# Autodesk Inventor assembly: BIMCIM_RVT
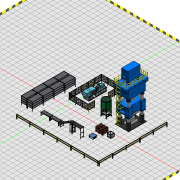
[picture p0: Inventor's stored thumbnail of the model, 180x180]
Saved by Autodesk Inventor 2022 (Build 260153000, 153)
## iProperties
Created: 2021-04
Part Number: BIMCIM_RVT
Document SubType Name: Assembly
Designer: shimont
Author: shimont
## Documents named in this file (16)
- C:\Users\shimont\Desktop\Inventor2022_BIMCIM出力\Inventor_Data\Workspaces\作業スペース\BIMCIM_RVT.iam
- C:\Users\shimont\Desktop\Inventor2022_BIMCIM出力\Inventor_Data\Workspaces\作業スペース\Factory Assets\Straight Belt Conveyor_62AB7746C87F18CB2B8D9DA90091859B.ipt
- C:\Users\shimont\Desktop\Inventor2022_BIMCIM出力\Inventor_Data\Workspaces\作業スペース\Factory Assets\Inclined Belt Conveyor_BBAA08BEB62DBBBFF53098BD601E2EAB.ipt
- C:\Users\shimont\Desktop\Inventor2022_BIMCIM出力\Inventor_Data\Workspaces\作業スペース\Factory Assets\Straight Belt Conveyor_1305EE5B90894E3F8A0AC29B882C3BD2.ipt
- C:\Users\shimont\Desktop\Inventor2022_BIMCIM出力\Inventor_Data\Workspaces\作業スペース\Factory Assets\Guard Rail_DAA5105E75A682DEC81597EA9AEDF0DA.ipt
- C:\Users\shimont\Desktop\Inventor2022_BIMCIM出力\Inventor_Data\Workspaces\作業スペース\Factory Assets\Guard Rail (Turn)_2788CAD562E2371D18F7DFFD656164ED.ipt
- C:\Users\shimont\Desktop\Inventor2022_BIMCIM出力\Inventor_Data\Workspaces\作業スペース\Factory Assets\Crate_83A1AEDB755784B46B9D26325E66DF3A.ipt
- C:\Users\shimont\Desktop\Inventor2022_BIMCIM出力\Inventor_Data\Workspaces\作業スペース\Factory Assets\Container (Mesh)_BC0053C154BD38D42D015A9FC74D4A9F.ipt
- C:\Users\shimont\Desktop\Inventor2022_BIMCIM出力\Inventor_Data\Workspaces\作業スペース\Factory Assets\Rack_49CEDE8AAA8C23DD442531F5BABC324C.ipt
- C:\Users\shimont\Desktop\Inventor2022_BIMCIM出力\Inventor_Data\Workspaces\作業スペース\Factory Assets\Lift Table_ED15CC229C601761F49F94E97E517109.ipt
- C:\Users\shimont\Desktop\Inventor2022_BIMCIM出力\Inventor_Data\Workspaces\作業スペース\Factory Assets\Forging Hydraulic Press_FF96057043D5FA31CE447ECF96B5AD74.ipt
- C:\Users\shimont\Desktop\Inventor2022_BIMCIM出力\Inventor_Data\Workspaces\作業スペース\Factory Assets\Vertical Blender_B7AA12CF308581BABF2536DA422488B5.ipt
- C:\Users\shimont\Desktop\Inventor2022_BIMCIM出力\Inventor_Data\Workspaces\作業スペース\Factory Assets\Injection Molding Machine_A8809DB1706EB9883261279B6DADA9EB.ipt
- C:\Users\shimont\Desktop\Inventor2022_BIMCIM出力\Inventor_Data\Workspaces\作業スペース\Factory Assets\Safety Fence (Turn For Asset Chains)_3DAE86F1382E41C33ACF8F022E66FD50.ipt
- C:\Users\shimont\Desktop\Inventor2022_BIMCIM出力\Inventor_Data\Workspaces\作業スペース\Factory Assets\Safety Fence (For Asset Chains)_EBBD1099C046A123A3332DC6DA49EF25.ipt
- C:\Users\shimont\Desktop\Inventor2022_BIMCIM出力\Inventor_Data\Workspaces\作業スペース\Factory Assets\Safety Fence (Turn)_AE1384E2C6E4AEBE8A5180D575C7EB08.ipt
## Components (21 placed, 14 different names)
1. 直進ベルト コンベア:1 — 直進ベルト コンベア:1_Floor, フラッシュ:2, メイト:1, メイト:2
2. 直進ベルト コンベア:2 — フラッシュ:2, メイト:1, メイト:2, フラッシュ:3, メイト:3, メイト:4
3. 傾斜ベルト コンベア:1 — フラッシュ:3, メイト:3, メイト:4, フラッシュ:4, メイト:5, メイト:6
4. 直進ベルト コンベア:3 — フラッシュ:4, メイト:5, メイト:6
5. ガード レール:1 — ガード レール:1_Floor, フラッシュ:5, メイト:8, メイト:9
6. ガード レール:2 — フラッシュ:5, メイト:8, メイト:9, フラッシュ:6, メイト:10, メイト:11
7. ガード レール(ターン):1 — フラッシュ:6, メイト:10, メイト:11, フラッシュ:7, メイト:12, メイト:13
8. ガード レール:3 — フラッシュ:7, メイト:12, メイト:13, フラッシュ:9, メイト:22, メイト:23
9. クレート:1 — クレート:1_Floor
10. コンテナ(メッシュ):1 — コンテナ(メッシュ):1_Floor
11. ラック:1 — ラック:1_Floor
12. リフト テーブル:1
13. 油圧式鍛造プレス:1
14. 垂直ブレンダ:1
15. インジェクション モールディング マシン:1
16. ガード レール:4 — フラッシュ:9, メイト:22, メイト:23
17. 安全柵(アセット チェーン用のターン):1 — 安全柵(アセット チェーン用のターン):1_Floor, フラッシュ:10, メイト:25, メイト:26, フラッシュ:13, メイト:31, メイト:32
18. 安全柵(アセット チェーン用):1 — フラッシュ:10, メイト:25, メイト:26, フラッシュ:11, メイト:27, メイト:28
19. 安全柵(アセット チェーン用のターン):2 — フラッシュ:11, メイト:27, メイト:28, フラッシュ:12, メイト:29, メイト:30
20. 安全柵(アセット チェーン用のターン):3 — フラッシュ:12, メイト:29, メイト:30
21. 安全柵(ターン):1 — フラッシュ:13, メイト:31, メイト:32
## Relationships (39: Mate 27, Flush 12)
- 直進ベルト コンベア:1_Floor [Flush]: 直進ベルト コンベア:1
- フラッシュ:2 [Flush]: 直進ベルト コンベア:1 ↔ 直進ベルト コンベア:2
- メイト:1 [Mate]: 直進ベルト コンベア:1 ↔ 直進ベルト コンベア:2
- メイト:2 [Mate]: 直進ベルト コンベア:1 ↔ 直進ベルト コンベア:2
- フラッシュ:3 [Flush]: 直進ベルト コンベア:2 ↔ 傾斜ベルト コンベア:1
- メイト:3 [Mate]: 直進ベルト コンベア:2 ↔ 傾斜ベルト コンベア:1
- メイト:4 [Mate]: 直進ベルト コンベア:2 ↔ 傾斜ベルト コンベア:1
- フラッシュ:4 [Flush]: 傾斜ベルト コンベア:1 ↔ 直進ベルト コンベア:3
- メイト:5 [Mate]: 傾斜ベルト コンベア:1 ↔ 直進ベルト コンベア:3
- メイト:6 [Mate]: 傾斜ベルト コンベア:1 ↔ 直進ベルト コンベア:3
- ガード レール:1_Floor [Mate]: ガード レール:1
- フラッシュ:5 [Flush]: ガード レール:1 ↔ ガード レール:2
- メイト:8 [Mate]: ガード レール:1 ↔ ガード レール:2
- メイト:9 [Mate]: ガード レール:1 ↔ ガード レール:2
- フラッシュ:6 [Flush]: ガード レール:2 ↔ ガード レール(ターン):1
- メイト:10 [Mate]: ガード レール:2 ↔ ガード レール(ターン):1
- メイト:11 [Mate]: ガード レール:2 ↔ ガード レール(ターン):1
- フラッシュ:7 [Flush]: ガード レール(ターン):1 ↔ ガード レール:3
- メイト:12 [Mate]: ガード レール(ターン):1 ↔ ガード レール:3
- メイト:13 [Mate]: ガード レール(ターン):1 ↔ ガード レール:3
- クレート:1_Floor [Mate]: クレート:1
- コンテナ(メッシュ):1_Floor [Mate]: コンテナ(メッシュ):1
- ラック:1_Floor [Mate]: ラック:1
- フラッシュ:9 [Flush]: ガード レール:3 ↔ ガード レール:4
- メイト:22 [Mate]: ガード レール:3 ↔ ガード レール:4
- メイト:23 [Mate]: ガード レール:3 ↔ ガード レール:4
- 安全柵(アセット チェーン用のターン):1_Floor [Mate]: 安全柵(アセット チェーン用のターン):1
- フラッシュ:10 [Flush]: 安全柵(アセット チェーン用のターン):1 ↔ 安全柵(アセット チェーン用):1
- メイト:25 [Mate]: 安全柵(アセット チェーン用のターン):1 ↔ 安全柵(アセット チェーン用):1
- メイト:26 [Mate]: 安全柵(アセット チェーン用のターン):1 ↔ 安全柵(アセット チェーン用):1
- フラッシュ:11 [Flush]: 安全柵(アセット チェーン用):1 ↔ 安全柵(アセット チェーン用のターン):2
- メイト:27 [Mate]: 安全柵(アセット チェーン用):1 ↔ 安全柵(アセット チェーン用のターン):2
- メイト:28 [Mate]: 安全柵(アセット チェーン用):1 ↔ 安全柵(アセット チェーン用のターン):2
- フラッシュ:12 [Flush]: 安全柵(アセット チェーン用のターン):2 ↔ 安全柵(アセット チェーン用のターン):3
- メイト:29 [Mate]: 安全柵(アセット チェーン用のターン):2 ↔ 安全柵(アセット チェーン用のターン):3
- メイト:30 [Mate]: 安全柵(アセット チェーン用のターン):2 ↔ 安全柵(アセット チェーン用のターン):3
- フラッシュ:13 [Flush]: 安全柵(アセット チェーン用のターン):1 ↔ 安全柵(ターン):1
- メイト:31 [Mate]: 安全柵(アセット チェーン用のターン):1 ↔ 安全柵(ターン):1
- メイト:32 [Mate]: 安全柵(アセット チェーン用のターン):1 ↔ 安全柵(ターン):1
